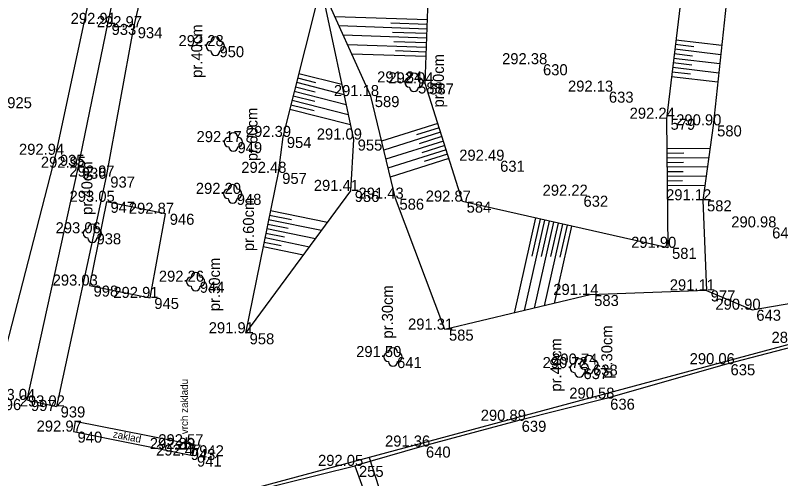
# Model space of a CAD drawing. Extents: x -599970 to -599524, y -1154772 to -1154457.
# Drawn here: x -599744.41 to -599702.82, y -1154661 to -1154635.85 of the extents above; entities that cross this region are included whole.
import ezdxf

# ---------------------------------------------------------------- set-up
doc = ezdxf.new("R2010")
doc.units = 0
for name, color, linetype in [('Z-KATASTRALNI MAPA', 7, 'Continuous'), ('Z-PLOT DRATENY', 7, 'Continuous'), ('Z-PODROBNE BODY', 7, 'Continuous'), ('Z-PODROBNE BODY-CISLO', 7, 'Continuous'), ('Z-PODROBNE BODY-VYSKA', 7, 'Continuous'), ('Z-POPISY OBJEKTU A ZPEVNENYCH PLOCH', 7, 'Continuous'), ('Z-PRUMERY KMENU STROMU', 7, 'Continuous'), ('Z-SRAFOVANI SVAHU', 7, 'Continuous'), ('Z-STROMY ZNACKY KULTUR', 7, 'Continuous'), ('Z-TERENNI HRANY PATY', 7, 'Continuous'), ('Z-VYSKOVE BODY', 7, 'Continuous'), ('Z-ZPEVNENE PLOCHY', 7, 'Continuous')]:
    doc.layers.add(name, color=color, linetype=linetype)

msp = doc.modelspace()

# ---------------------------------------------------------------- linework, layer by layer
at = {"layer": 'Z-KATASTRALNI MAPA'}
for p, q in [((-599685.27, -1154649.13), (-599725.18, -1154659.85)), ((-599725.18, -1154659.85), (-599770.56, -1154672.04)), ((-599725.18, -1154659.85), (-599721.27, -1154672.07))]:
    msp.add_line(p, q, dxfattribs=at)
at = {"layer": 'Z-PLOT DRATENY'}
for points in [[(-599790.59, -1154625.68), (-599789.41, -1154629.89), (-599785.15, -1154644.86), (-599782.34, -1154653.87), (-599779.13, -1154664.86), (-599776.51, -1154673.7), (-599770.19, -1154672.08), (-599762.65, -1154670.15), (-599753.18, -1154667.49), (-599743.82, -1154665.08), (-599731.66, -1154661.71), (-599725.96, -1154660.31)], [(-599745.65, -1154656.68), (-599742.21, -1154643.42), (-599738.73, -1154627.21)], [(-599687.21, -1154649.64), (-599693.32, -1154651.37), (-599701.32, -1154653.63), (-599705.77, -1154654.79), (-599712.31, -1154656.66), (-599717.12, -1154657.86), (-599722.32, -1154659.26), (-599725.96, -1154660.31)], [(-599725.96, -1154660.31), (-599725.45, -1154661.7), (-599724.95, -1154663.59)]]:
    msp.add_lwpolyline(points, dxfattribs=at)
at = {"layer": 'Z-PODROBNE BODY'}
for p, q in [((-599739.4, -1154636.31), (-599739.4, -1154636.31)), ((-599737.98, -1154636.49), (-599737.98, -1154636.49)), ((-599733.54, -1154637.52), (-599733.54, -1154637.52)), ((-599715.96, -1154638.5), (-599715.96, -1154638.5)), ((-599722.75, -1154639.49), (-599722.75, -1154639.49)), ((-599722.14, -1154639.54), (-599722.14, -1154639.54)), ((-599725.1, -1154640.23), (-599725.1, -1154640.23)), ((-599712.38, -1154639.99), (-599712.38, -1154639.99)), ((-599709.03, -1154641.46), (-599709.03, -1154641.46)), ((-599706.5, -1154641.82), (-599706.5, -1154641.82)), ((-599729.88, -1154642.45), (-599729.88, -1154642.45)), ((-599732.56, -1154642.73), (-599732.56, -1154642.73)), ((-599726.03, -1154642.59), (-599726.03, -1154642.59)), ((-599742.21, -1154643.42), (-599742.21, -1154643.42)), ((-599741.02, -1154644.12), (-599741.02, -1154644.12)), ((-599718.29, -1154643.74), (-599718.29, -1154643.74)), ((-599730.13, -1154644.4), (-599730.13, -1154644.4)), ((-599739.47, -1154644.6), (-599739.47, -1154644.6)), ((-599732.6, -1154645.54), (-599732.6, -1154645.54)), ((-599726.19, -1154645.38), (-599726.19, -1154645.38)), ((-599713.76, -1154645.64), (-599713.76, -1154645.64)), ((-599739.46, -1154645.97), (-599739.46, -1154645.97)), ((-599723.76, -1154645.8), (-599723.76, -1154645.8)), ((-599720.11, -1154645.96), (-599720.11, -1154645.96)), ((-599707.05, -1154645.89), (-599707.05, -1154645.89)), ((-599736.24, -1154646.62), (-599736.24, -1154646.62)), ((-599703.51, -1154647.36), (-599703.51, -1154647.36)), ((-599740.22, -1154647.68), (-599740.22, -1154647.68)), ((-599708.95, -1154648.47), (-599708.95, -1154648.47)), ((-599734.61, -1154650.31), (-599734.61, -1154650.31)), ((-599740.38, -1154650.52), (-599740.38, -1154650.52)), ((-599706.85, -1154650.78), (-599706.85, -1154650.78)), ((-599737.08, -1154651.19), (-599737.08, -1154651.19)), ((-599713.18, -1154651.03), (-599713.18, -1154651.03)), ((-599704.37, -1154651.83), (-599704.37, -1154651.83)), ((-599731.9, -1154653.11), (-599731.9, -1154653.11)), ((-599721.07, -1154652.91), (-599721.07, -1154652.91)), ((-599723.89, -1154654.4), (-599723.89, -1154654.4)), ((-599713.24, -1154654.81), (-599713.24, -1154654.81)), ((-599705.77, -1154654.79), (-599705.77, -1154654.79)), ((-599713.76, -1154655), (-599713.76, -1154655)), ((-599743.78, -1154656.73), (-599743.78, -1154656.73)), ((-599712.31, -1154656.66), (-599712.31, -1154656.66)), ((-599742.17, -1154657.08), (-599742.17, -1154657.08)), ((-599717.12, -1154657.86), (-599717.12, -1154657.86)), ((-599741.25, -1154658.45), (-599741.25, -1154658.45)), ((-599735.1, -1154659.39), (-599735.1, -1154659.39)), ((-599734.64, -1154659.19), (-599734.64, -1154659.19)), ((-599722.32, -1154659.26), (-599722.32, -1154659.26)), ((-599734.76, -1154659.75), (-599734.76, -1154659.75)), ((-599725.96, -1154660.31), (-599725.96, -1154660.31))]:
    msp.add_line(p, q, dxfattribs=at)
at = {"layer": 'Z-SRAFOVANI SVAHU'}
for points in [[(-599722.02, -1154636.09), (-599727.04, -1154635.92)], [(-599722.04, -1154636.59), (-599726.82, -1154636.42)], [(-599722.03, -1154636.34), (-599724, -1154636.27)], [(-599722.05, -1154637.09), (-599726.59, -1154636.93)], [(-599722.05, -1154636.84), (-599723.92, -1154636.78)], [(-599722.07, -1154637.59), (-599726.36, -1154637.44)], [(-599722.06, -1154637.34), (-599723.84, -1154637.28)], [(-599708.55, -1154637.42), (-599707.55, -1154637.54)], [(-599708.52, -1154637.17), (-599706.03, -1154637.47)], [(-599722.08, -1154637.84), (-599723.76, -1154637.78)], [(-599708.58, -1154637.67), (-599706.08, -1154637.97)], [(-599722.09, -1154638.09), (-599726.13, -1154637.95)], [(-599708.64, -1154638.17), (-599706.13, -1154638.47)], [(-599708.61, -1154637.92), (-599707.61, -1154638.04)], [(-599708.69, -1154638.66), (-599706.19, -1154638.96)], [(-599708.67, -1154638.41), (-599707.66, -1154638.53)], [(-599729.01, -1154639), (-599726.67, -1154639.59)], [(-599708.72, -1154638.91), (-599707.72, -1154639.03)], [(-599729.13, -1154639.48), (-599726.56, -1154640.14)], [(-599729.07, -1154639.24), (-599728.09, -1154639.49)], [(-599708.75, -1154639.16), (-599706.24, -1154639.46)], [(-599729.25, -1154639.97), (-599726.44, -1154640.68)], [(-599729.19, -1154639.73), (-599728.11, -1154640)], [(-599729.31, -1154640.21), (-599728.14, -1154640.51)], [(-599729.44, -1154640.7), (-599728.17, -1154641.02)], [(-599729.37, -1154640.45), (-599726.32, -1154641.23)], [(-599729.5, -1154640.94), (-599726.2, -1154641.77)], [(-599721.45, -1154641.72), (-599724.51, -1154642.68)], [(-599721.38, -1154641.96), (-599722.61, -1154642.34)], [(-599721.3, -1154642.19), (-599724.39, -1154643.17)], [(-599721.23, -1154642.43), (-599722.47, -1154642.83)], [(-599721.15, -1154642.67), (-599724.28, -1154643.66)], [(-599721, -1154643.15), (-599724.16, -1154644.15)], [(-599721.07, -1154642.91), (-599722.33, -1154643.31)], [(-599709.01, -1154643.08), (-599706.67, -1154643.05)], [(-599720.85, -1154643.62), (-599724.04, -1154644.63)], [(-599720.92, -1154643.39), (-599722.19, -1154643.79)], [(-599709.01, -1154643.33), (-599708.09, -1154643.32)], [(-599709.01, -1154643.58), (-599706.73, -1154643.56)], [(-599709, -1154643.83), (-599708.11, -1154643.82)], [(-599709, -1154644.08), (-599706.8, -1154644.06)], [(-599709, -1154644.33), (-599708.13, -1154644.32)], [(-599708.99, -1154644.58), (-599706.87, -1154644.56)], [(-599708.99, -1154644.83), (-599708.16, -1154644.82)], [(-599708.99, -1154645.08), (-599706.94, -1154645.06)], [(-599730.55, -1154646.44), (-599727.44, -1154647.08)], [(-599730.65, -1154646.93), (-599727.77, -1154647.52)], [(-599730.6, -1154646.69), (-599729.4, -1154646.93)], [(-599716.14, -1154646.85), (-599717.3, -1154652.01)], [(-599715.65, -1154646.96), (-599716.76, -1154651.88)], [(-599715.89, -1154646.91), (-599716.35, -1154648.92)], [(-599715.41, -1154647.02), (-599715.84, -1154648.94)], [(-599730.74, -1154647.42), (-599728.1, -1154647.96)], [(-599730.69, -1154647.18), (-599729.59, -1154647.4)], [(-599715.16, -1154647.07), (-599716.21, -1154651.75)], [(-599714.67, -1154647.18), (-599715.67, -1154651.62)], [(-599714.92, -1154647.13), (-599715.33, -1154648.95)], [(-599714.19, -1154647.29), (-599715.13, -1154651.49)], [(-599714.43, -1154647.24), (-599714.82, -1154648.97)], [(-599730.79, -1154647.67), (-599729.78, -1154647.88)], [(-599730.89, -1154648.16), (-599729.97, -1154648.35)], [(-599730.84, -1154647.91), (-599728.43, -1154648.41)], [(-599730.94, -1154648.4), (-599728.75, -1154648.85)]]:
    msp.add_lwpolyline(points, dxfattribs=at)
at = {"layer": 'Z-STROMY ZNACKY KULTUR'}
for centre in [(-599733.54, -1154637.52), (-599722.75, -1154639.49), (-599732.56, -1154642.73), (-599732.6, -1154645.54), (-599740.22, -1154647.68), (-599734.61, -1154650.31), (-599723.89, -1154654.4), (-599713.24, -1154654.81), (-599713.76, -1154655)]:
    msp.add_circle(centre, 0.00025, dxfattribs=at)
for centre, start, end in [((-599733.54, -1154637.27), 0, 180), ((-599733.79, -1154637.52), 90, 270), ((-599733.29, -1154637.52), 270, 90), ((-599733.54, -1154637.77), 180, 360), ((-599722.75, -1154639.24), 0, 180), ((-599723, -1154639.49), 90, 270), ((-599722.5, -1154639.49), 270, 90), ((-599722.75, -1154639.74), 180, 360), ((-599732.56, -1154642.48), 0, 180), ((-599732.81, -1154642.73), 90, 270), ((-599732.31, -1154642.73), 270, 90), ((-599732.56, -1154642.98), 180, 360), ((-599732.85, -1154645.54), 90, 270), ((-599732.6, -1154645.29), 0, 180), ((-599732.35, -1154645.54), 270, 90), ((-599732.6, -1154645.79), 180, 360), ((-599740.47, -1154647.68), 90, 270), ((-599740.22, -1154647.43), 0, 180), ((-599739.97, -1154647.68), 270, 90), ((-599740.22, -1154647.93), 180, 360), ((-599734.61, -1154650.06), 0, 180), ((-599734.86, -1154650.31), 90, 270), ((-599734.36, -1154650.31), 270, 90), ((-599734.61, -1154650.56), 180, 360), ((-599723.89, -1154654.15), 0, 180), ((-599724.14, -1154654.4), 90, 270), ((-599723.64, -1154654.4), 270, 90), ((-599713.76, -1154654.75), 0, 180), ((-599713.24, -1154654.56), 0, 180), ((-599723.89, -1154654.65), 180, 360), ((-599714.01, -1154655), 90, 270), ((-599713.49, -1154654.81), 90, 270), ((-599713.51, -1154655), 270, 90), ((-599712.99, -1154654.81), 270, 90), ((-599713.76, -1154655.25), 180, 360), ((-599713.24, -1154655.06), 180, 360)]:
    msp.add_arc(centre, 0.25, start, end, dxfattribs=at)
at = {"layer": 'Z-TERENNI HRANY PATY'}
for points in [[(-599702.71, -1154612.59), (-599703.07, -1154620.17), (-599705.22, -1154630.05), (-599705.67, -1154634.21), (-599706.5, -1154641.82), (-599707.05, -1154645.89), (-599706.85, -1154650.78)], [(-599706.85, -1154650.78), (-599713.18, -1154651.03), (-599721.07, -1154652.91), (-599723.76, -1154645.8), (-599725.1, -1154640.23), (-599727.83, -1154634.18), (-599728.54, -1154633), (-599732.31, -1154631.05), (-599735.11, -1154628.08), (-599735.76, -1154623.86), (-599735.73, -1154623.89), (-599734.76, -1154621.33), (-599730.32, -1154616.62), (-599722.93, -1154615.52), (-599713.66, -1154613.52), (-599712.4, -1154614.76), (-599710.05, -1154618.59), (-599710.54, -1154622.05), (-599712.9, -1154623.66), (-599717.25, -1154628.18), (-599716.96, -1154629.04), (-599714.58, -1154631.6), (-599714.4, -1154633.54), (-599711.28, -1154633.06)], [(-599704.68, -1154613.79), (-599704.97, -1154620.78), (-599707.54, -1154629.53), (-599708.11, -1154633.78), (-599709.03, -1154641.46), (-599708.95, -1154648.47), (-599720.11, -1154645.96), (-599722.14, -1154639.54), (-599721.91, -1154632.94), (-599724.31, -1154631.24), (-599726.05, -1154627.36), (-599728.73, -1154626.15), (-599733.01, -1154625.97), (-599733.06, -1154622.51), (-599729.32, -1154618.34), (-599722.3, -1154617.17), (-599714.17, -1154615.37), (-599711.22, -1154619.52), (-599712.8, -1154621.32)], [(-599737, -1154633.39), (-599728.04, -1154635.19), (-599729.88, -1154642.45), (-599730.13, -1154644.4), (-599731.9, -1154653.11)], [(-599727.83, -1154634.18), (-599726.03, -1154642.59), (-599726.19, -1154645.38), (-599731.9, -1154653.11)], [(-599706.85, -1154650.78), (-599704.37, -1154651.83), (-599696.59, -1154650.49), (-599697.61, -1154647.02), (-599698.31, -1154645.1), (-599699.48, -1154642.29)]]:
    msp.add_lwpolyline(points, dxfattribs=at)
at = {"layer": 'Z-VYSKOVE BODY'}
for p, q in [((-599735.1, -1154658.765), (-599735.1, -1154659.015)), ((-599735.1, -1154659.015), (-599735.1, -1154658.765)), ((-599735.1, -1154659.39), (-599735.1, -1154658.765)), ((-599735.1, -1154658.765), (-599735.1, -1154659.015)), ((-599734.475, -1154659.39), (-599735.725, -1154659.39)), ((-599735.725, -1154659.39), (-599735.1, -1154659.39)), ((-599734.475, -1154659.39), (-599735.1, -1154659.39))]:
    msp.add_line(p, q, dxfattribs=at)
for start, end in [(90, 180), (0, 90)]:
    msp.add_arc((-599735.1, -1154659.39), 0.375, start, end, dxfattribs=at)
at = {"layer": 'Z-ZPEVNENE PLOCHY'}
for points in [[(-599736.4, -1154629.74), (-599737.91, -1154629.39), (-599739.4, -1154636.31), (-599741.02, -1154644.12), (-599743.78, -1154656.73), (-599742.17, -1154657.08)], [(-599736.4, -1154629.74), (-599737.98, -1154636.49), (-599739.47, -1154644.6), (-599742.17, -1154657.08)], [(-599739.46, -1154645.97), (-599740.38, -1154650.52), (-599737.08, -1154651.19)], [(-599737.08, -1154651.19), (-599736.24, -1154646.62), (-599739.46, -1154645.97)], [(-599741.25, -1154658.45), (-599734.76, -1154659.75), (-599734.64, -1154659.19), (-599741.15, -1154657.9), (-599741.25, -1154658.45)]]:
    msp.add_lwpolyline(points, dxfattribs=at)

# ---------------------------------------------------------------- texts
at = {"layer": 'Z-PODROBNE BODY-CISLO'}
for s, p in [(' 933', (-599739.4, -1154636.91)), (' 934', (-599737.98, -1154637.09)), (' 950', (-599733.54, -1154638.12)), (' 630', (-599715.96, -1154639.1)), (' 588', (-599722.75, -1154640.09)), (' 587', (-599722.14, -1154640.14)), (' 925', (-599745.07, -1154640.89)), (' 589', (-599725.1, -1154640.83)), (' 633', (-599712.38, -1154640.59)), (' 579', (-599709.03, -1154642.06)), (' 580', (-599706.5, -1154642.42)), (' 954', (-599729.88, -1154643.05)), (' 949', (-599732.56, -1154643.33)), (' 955', (-599726.03, -1154643.19)), (' 935', (-599742.21, -1154644.02)), (' 936', (-599741.02, -1154644.72)), (' 631', (-599718.29, -1154644.34)), (' 957', (-599730.13, -1154645)), (' 937', (-599739.47, -1154645.2)), (' 956', (-599726.19, -1154645.98)), (' 948', (-599732.6, -1154646.14)), (' 586', (-599723.76, -1154646.4)), (' 632', (-599713.76, -1154646.24)), (' 947', (-599739.46, -1154646.57)), (' 584', (-599720.11, -1154646.56)), (' 582', (-599707.05, -1154646.49)), (' 946', (-599736.24, -1154647.22)), (' 642', (-599703.51, -1154647.96)), (' 938', (-599740.22, -1154648.28)), (' 581', (-599708.95, -1154649.07)), (' 944', (-599734.61, -1154650.91)), (' 998', (-599740.38, -1154651.12)), (' 977', (-599706.85, -1154651.38)), (' 945', (-599737.08, -1154651.79)), (' 583', (-599713.18, -1154651.63)), (' 643', (-599704.37, -1154652.43)), (' 958', (-599731.9, -1154653.71)), (' 585', (-599721.07, -1154653.51)), (' 641', (-599723.89, -1154655)), (' 638', (-599713.24, -1154655.41)), (' 635', (-599705.77, -1154655.39)), (' 637', (-599713.76, -1154655.6)), (' 996', (-599745.65, -1154657.28)), (' 997', (-599743.78, -1154657.33)), (' 636', (-599712.31, -1154657.26)), (' 939', (-599742.17, -1154657.68)), (' 639', (-599717.12, -1154658.46)), (' 940', (-599741.25, -1154659.05)), (' 943', (-599735.1, -1154659.99)), (' 942', (-599734.64, -1154659.79)), (' 640', (-599722.32, -1154659.86)), (' 941', (-599734.76, -1154660.35)), (' 255', (-599725.96, -1154660.91))]:
    msp.add_text(s, height=0.6, dxfattribs=at).set_placement(p)
at = {"layer": 'Z-PODROBNE BODY-VYSKA'}
for s, p in [('292.91 ', (-599741.4, -1154636.31)), ('292.97 ', (-599739.98, -1154636.49)), ('292.28 ', (-599735.54, -1154637.52)), ('292.38 ', (-599717.96, -1154638.5)), ('291.84 ', (-599724.75, -1154639.49)), ('292.04 ', (-599724.14, -1154639.54)), ('292.13 ', (-599714.38, -1154639.99)), ('291.18 ', (-599727.1, -1154640.23)), ('292.24 ', (-599711.03, -1154641.46)), ('290.90 ', (-599708.5, -1154641.82)), ('292.39 ', (-599731.88, -1154642.45)), ('291.09 ', (-599728.03, -1154642.59)), ('292.17 ', (-599734.56, -1154642.73)), ('292.94 ', (-599744.21, -1154643.42)), ('292.49 ', (-599720.29, -1154643.74)), ('292.95 ', (-599743.02, -1154644.12)), ('292.97 ', (-599741.47, -1154644.6)), ('292.48 ', (-599732.13, -1154644.4)), ('292.20 ', (-599734.6, -1154645.54)), ('291.41 ', (-599728.19, -1154645.38)), ('293.05 ', (-599741.46, -1154645.97)), ('291.43 ', (-599725.76, -1154645.8)), ('292.87 ', (-599722.11, -1154645.96)), ('292.22 ', (-599715.76, -1154645.64)), ('291.12 ', (-599709.05, -1154645.89)), ('292.87 ', (-599738.24, -1154646.62)), ('290.98 ', (-599705.51, -1154647.36)), ('293.06 ', (-599742.22, -1154647.68)), ('291.90 ', (-599710.95, -1154648.47)), ('293.03 ', (-599742.38, -1154650.52)), ('292.26 ', (-599736.61, -1154650.31)), ('291.11 ', (-599708.85, -1154650.78)), ('292.91 ', (-599739.08, -1154651.19)), ('291.14 ', (-599715.18, -1154651.03)), ('290.90 ', (-599706.37, -1154651.83)), ('291.31 ', (-599723.07, -1154652.91)), ('291.91 ', (-599733.9, -1154653.11)), ('289.88 ', (-599703.32, -1154653.63)), ('291.50 ', (-599725.89, -1154654.4)), ('290.72 ', (-599715.76, -1154655)), ('290.74 ', (-599715.24, -1154654.81)), ('290.06 ', (-599707.77, -1154654.79)), ('293.04 ', (-599745.78, -1154656.73)), ('290.58 ', (-599714.31, -1154656.66)), ('293.02 ', (-599744.17, -1154657.08)), ('290.89 ', (-599719.12, -1154657.86)), ('292.97 ', (-599743.25, -1154658.45)), ('292.57 ', (-599736.64, -1154659.19)), ('291.36 ', (-599724.32, -1154659.26)), ('292.89 ', (-599737.1, -1154659.39)), ('292.47 ', (-599736.76, -1154659.75)), ('292.05 ', (-599727.96, -1154660.31))]:
    msp.add_text(s, height=0.6, dxfattribs=at).set_placement(p)
at = {"layer": 'Z-POPISY OBJEKTU A ZPEVNENYCH PLOCH'}
msp.add_text('zaklad', height=0.4, rotation=348.6731, dxfattribs=at).set_placement((-599739.13, -1154658.76))
at = {"layer": 'Z-PRUMERY KMENU STROMU'}
for s, p in [('pr.40cm', (-599734.25, -1154639.24)), ('pr.40cm', (-599721.12, -1154640.85)), ('pr.60cm', (-599731.25, -1154643.76)), ('pr.40cm', (-599740.22, -1154646.68)), ('pr.60cm', (-599731.44, -1154648.65)), ('pr.30cm', (-599733.29, -1154651.91)), ('pr.30cm', (-599723.89, -1154653.4)), ('pr.30cm', (-599711.97, -1154655.58)), ('pr.40cm', (-599714.74, -1154656.28))]:
    msp.add_text(s, height=0.6, rotation=90, dxfattribs=at).set_placement(p)
at = {"layer": 'Z-VYSKOVE BODY'}
msp.add_text('vrch zakladu', height=0.4, rotation=90, dxfattribs=at).set_placement((-599735.03, -1154658.59))

doc.saveas('drawing.dxf')
